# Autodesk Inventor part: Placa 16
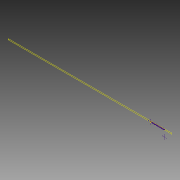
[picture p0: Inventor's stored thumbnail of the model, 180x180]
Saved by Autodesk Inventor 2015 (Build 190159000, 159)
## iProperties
Created: 2015-04
Part Number: Placa 16
Material: Generic
Document SubType Name: Modeling
Designer: suporte
Density: 1 g/cm^3
Appearance: Default
Author: suporte
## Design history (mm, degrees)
workplane "Work Plane1"
sketch "Sketch1"
  geometry: L1 (-2100, 0)-(-2100, 12.5) reference; L2 (-1900, 0)-(-2100, 0); L3 (-2100, 0)-(-2100, 12.5); L4 (-2100, 12.5)-(-1900, 12.5); L5 (-1900, 12.5)-(-1900, 0); 2 further points
  constraints: 8 end point, 2 parallel, 1 horizontal, 1 perpendicular, 2 other
extrude "Extrusion1" new body sketch "Sketch1" distance "d0" = 575; taper "d1" = 0 deg
body "Solid1"
node "Reference1"
